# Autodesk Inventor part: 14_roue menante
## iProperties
Shininess: 20.0
Length Units: 11270
Angle Units: 11279
Time Units: 11290
Mass Units: 11283
Length Display Precision: 3
Angle Display Precision: 2
Created: 2000-10
Part Number: 14_roue menante
Material: Par défaut
Document SubType Name: Modélisation
Density: 0.0
Volumn: 0.0
Area: 0.0
PropertySet Name: Model Information
Control State: 0
Master: False
Checked Out: False
Author: Laurent GAUTHERON
